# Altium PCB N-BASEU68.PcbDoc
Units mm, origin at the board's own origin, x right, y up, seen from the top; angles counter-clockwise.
Board outline 33.03 x 43.18 mm, 4 copper layers (Top Layer, Signal Layer 1, GND-PLANE, Bottom Layer), stack 1.583 mm thick; 51 components, 58 nets, 221 pads, 79 vias.
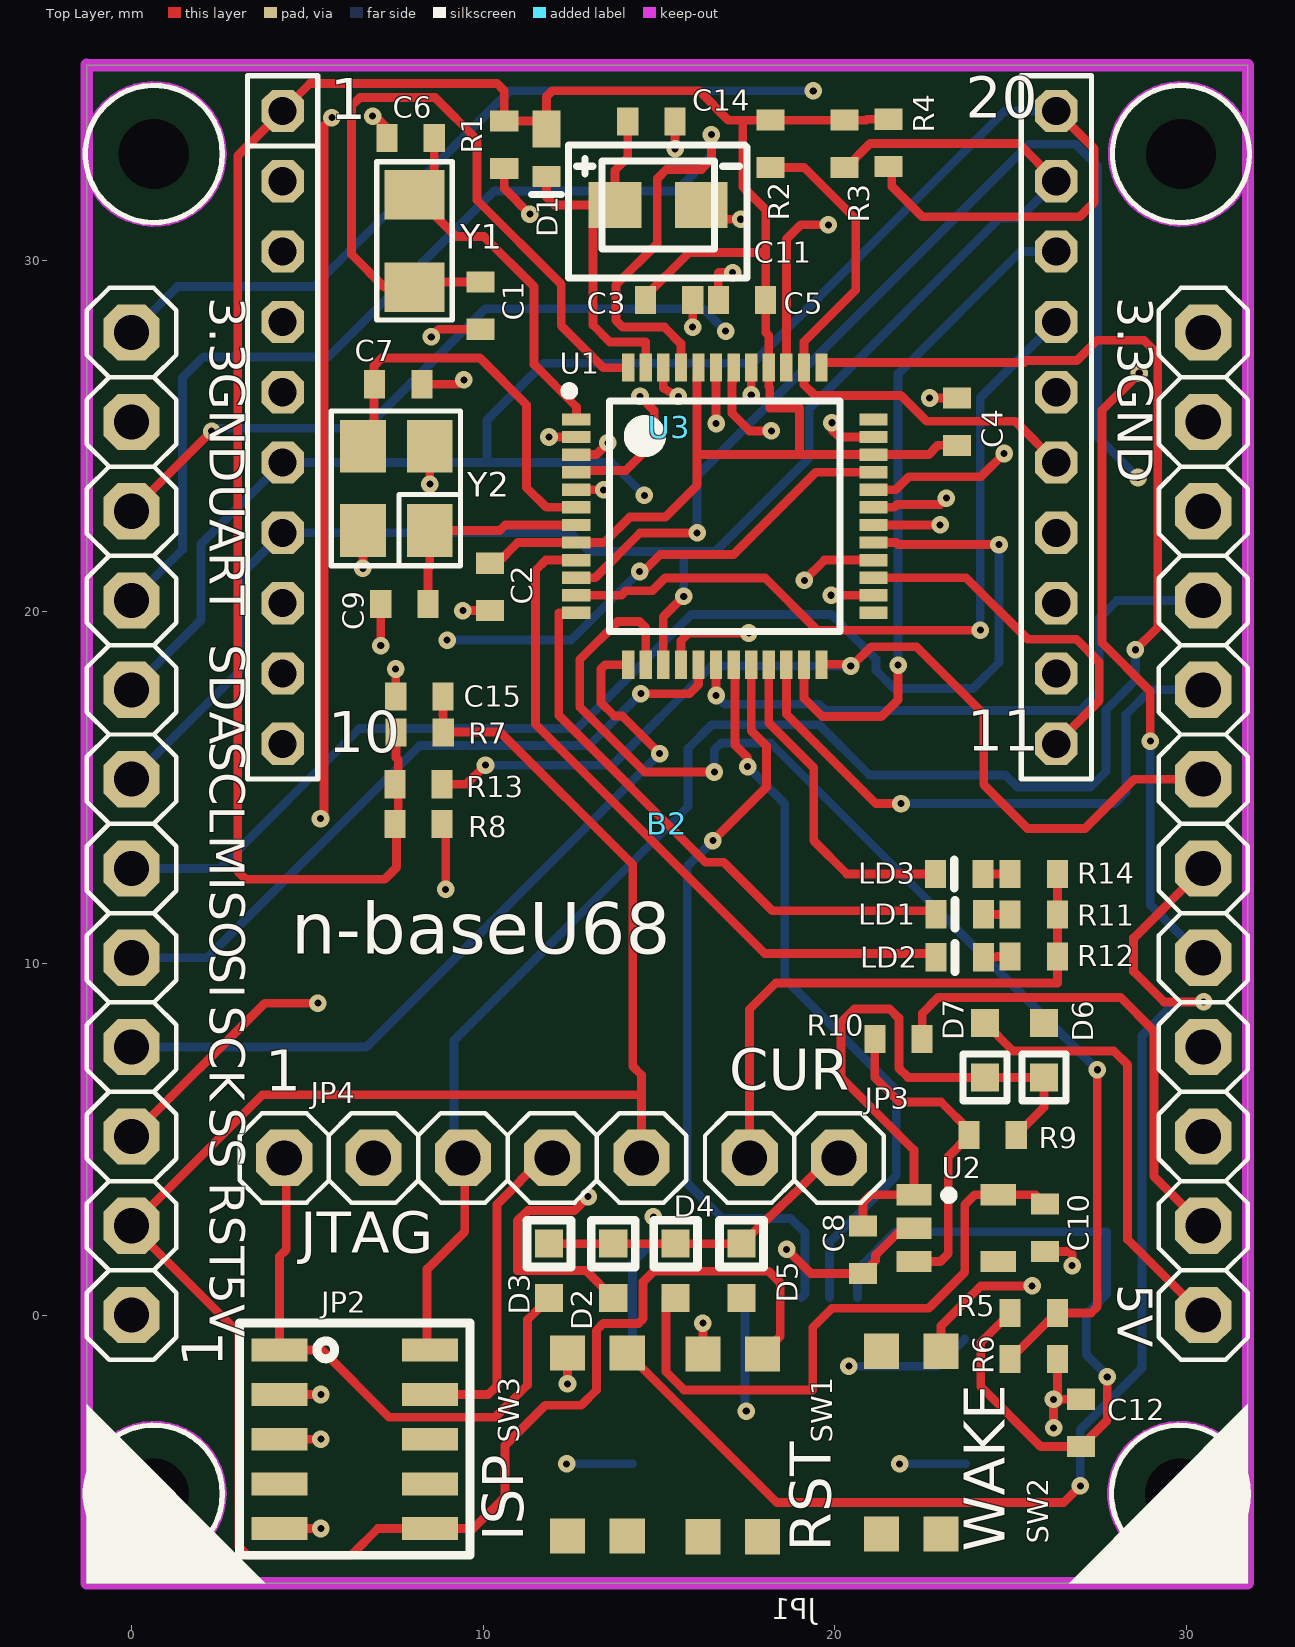
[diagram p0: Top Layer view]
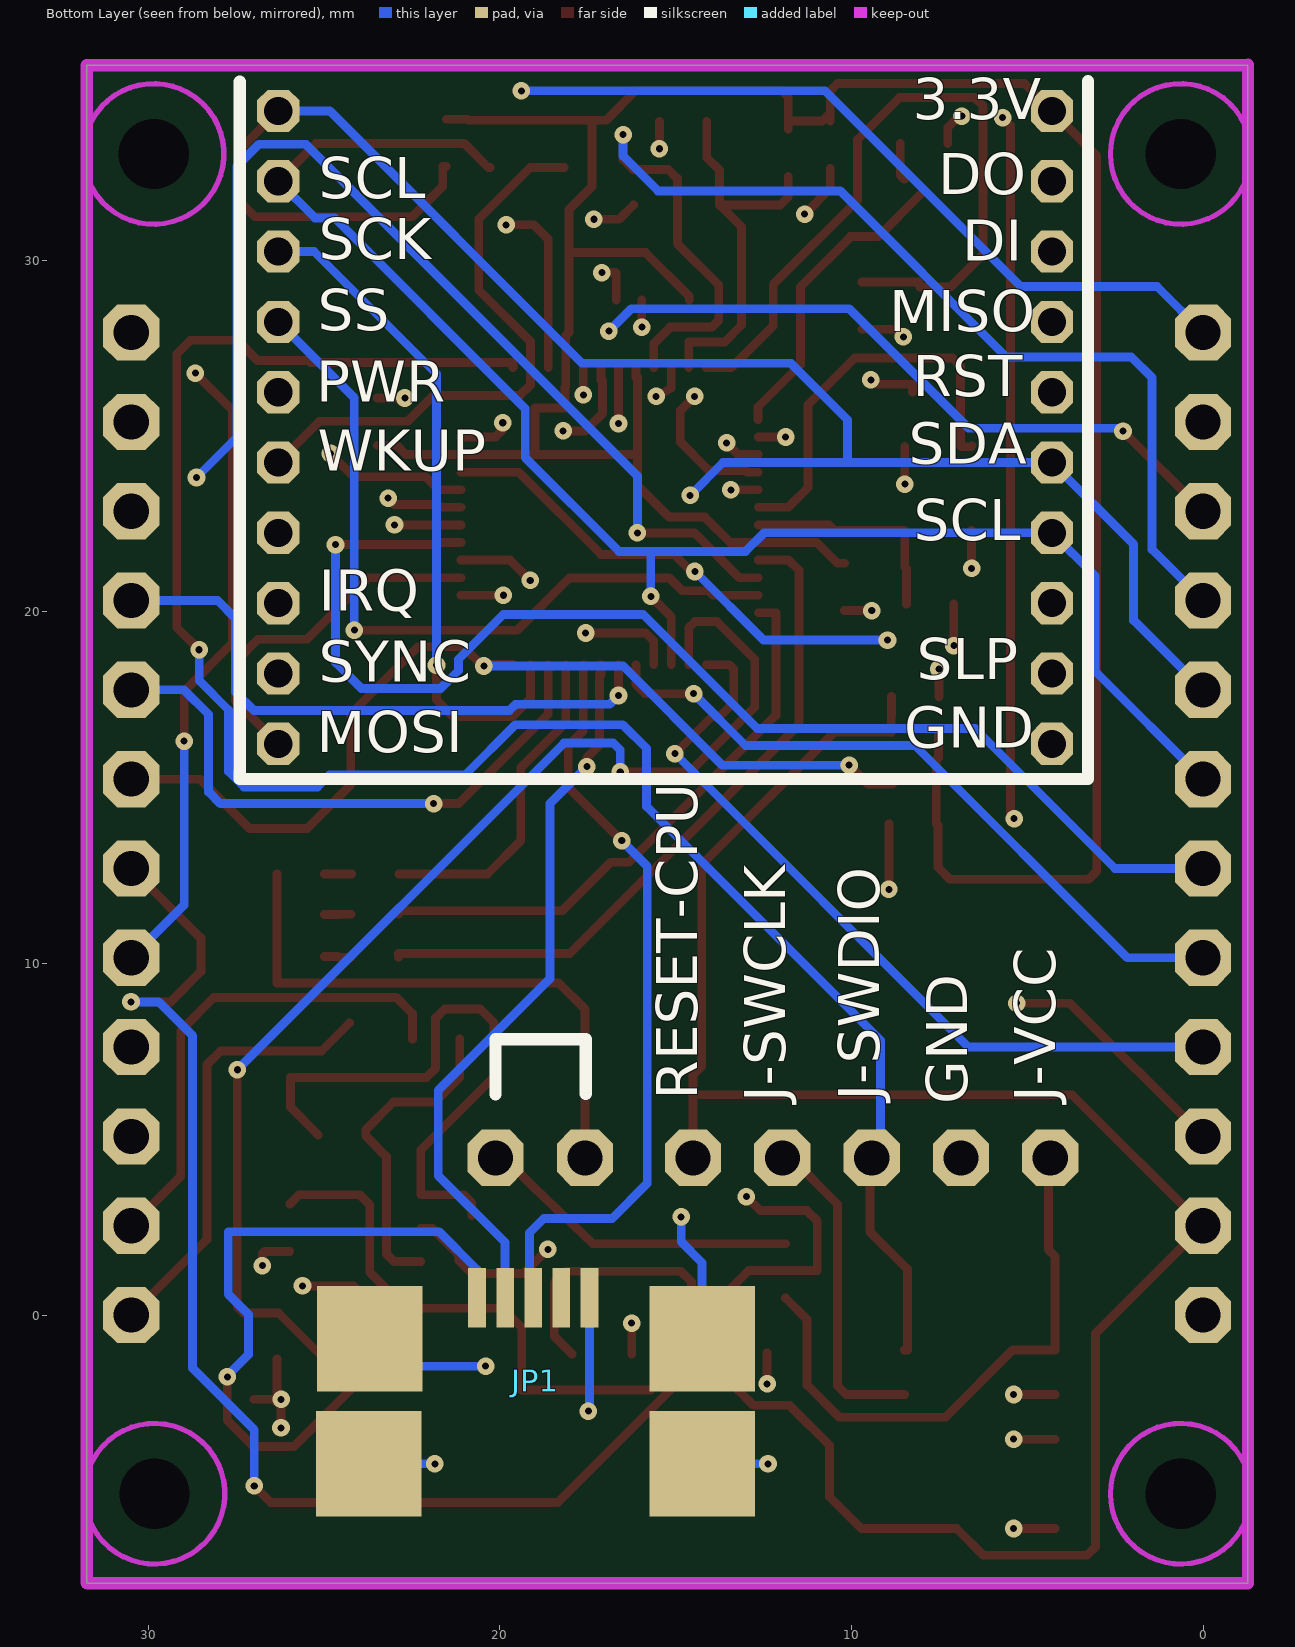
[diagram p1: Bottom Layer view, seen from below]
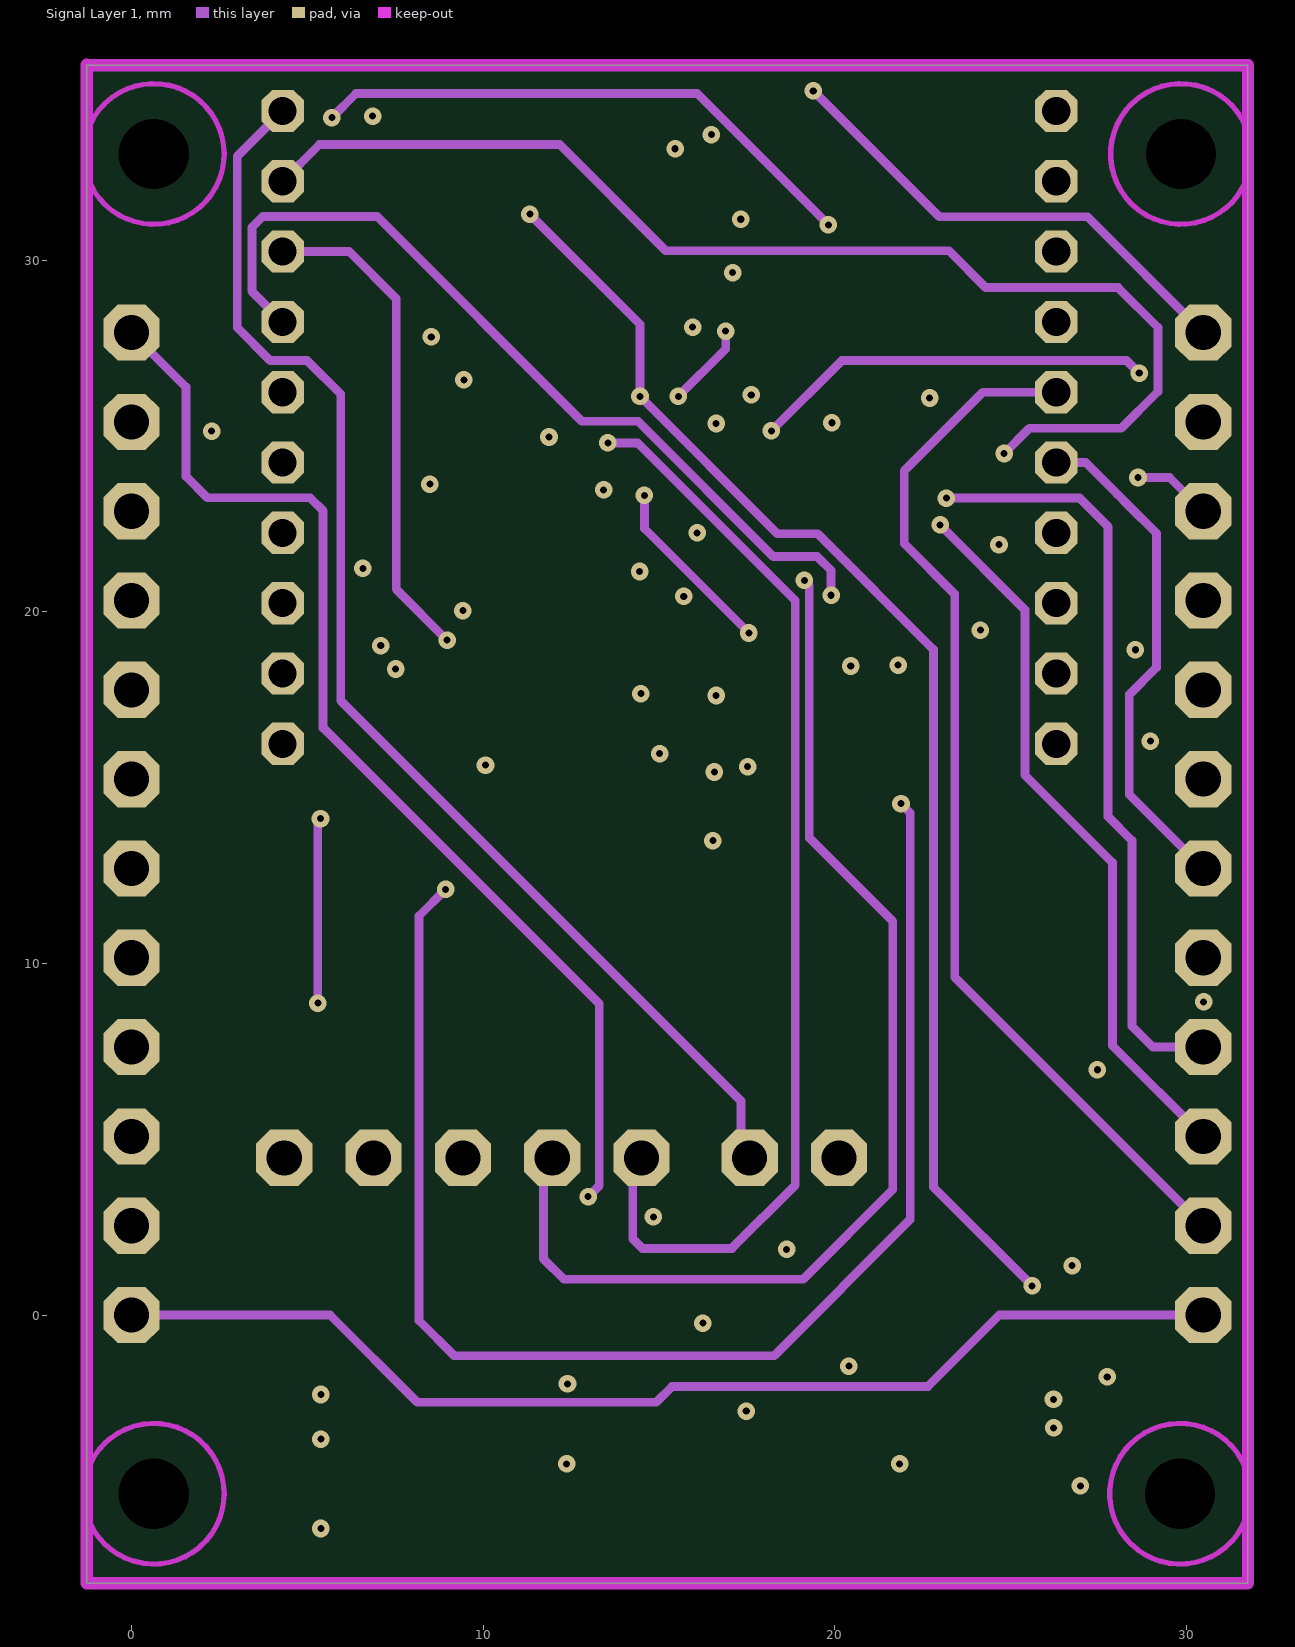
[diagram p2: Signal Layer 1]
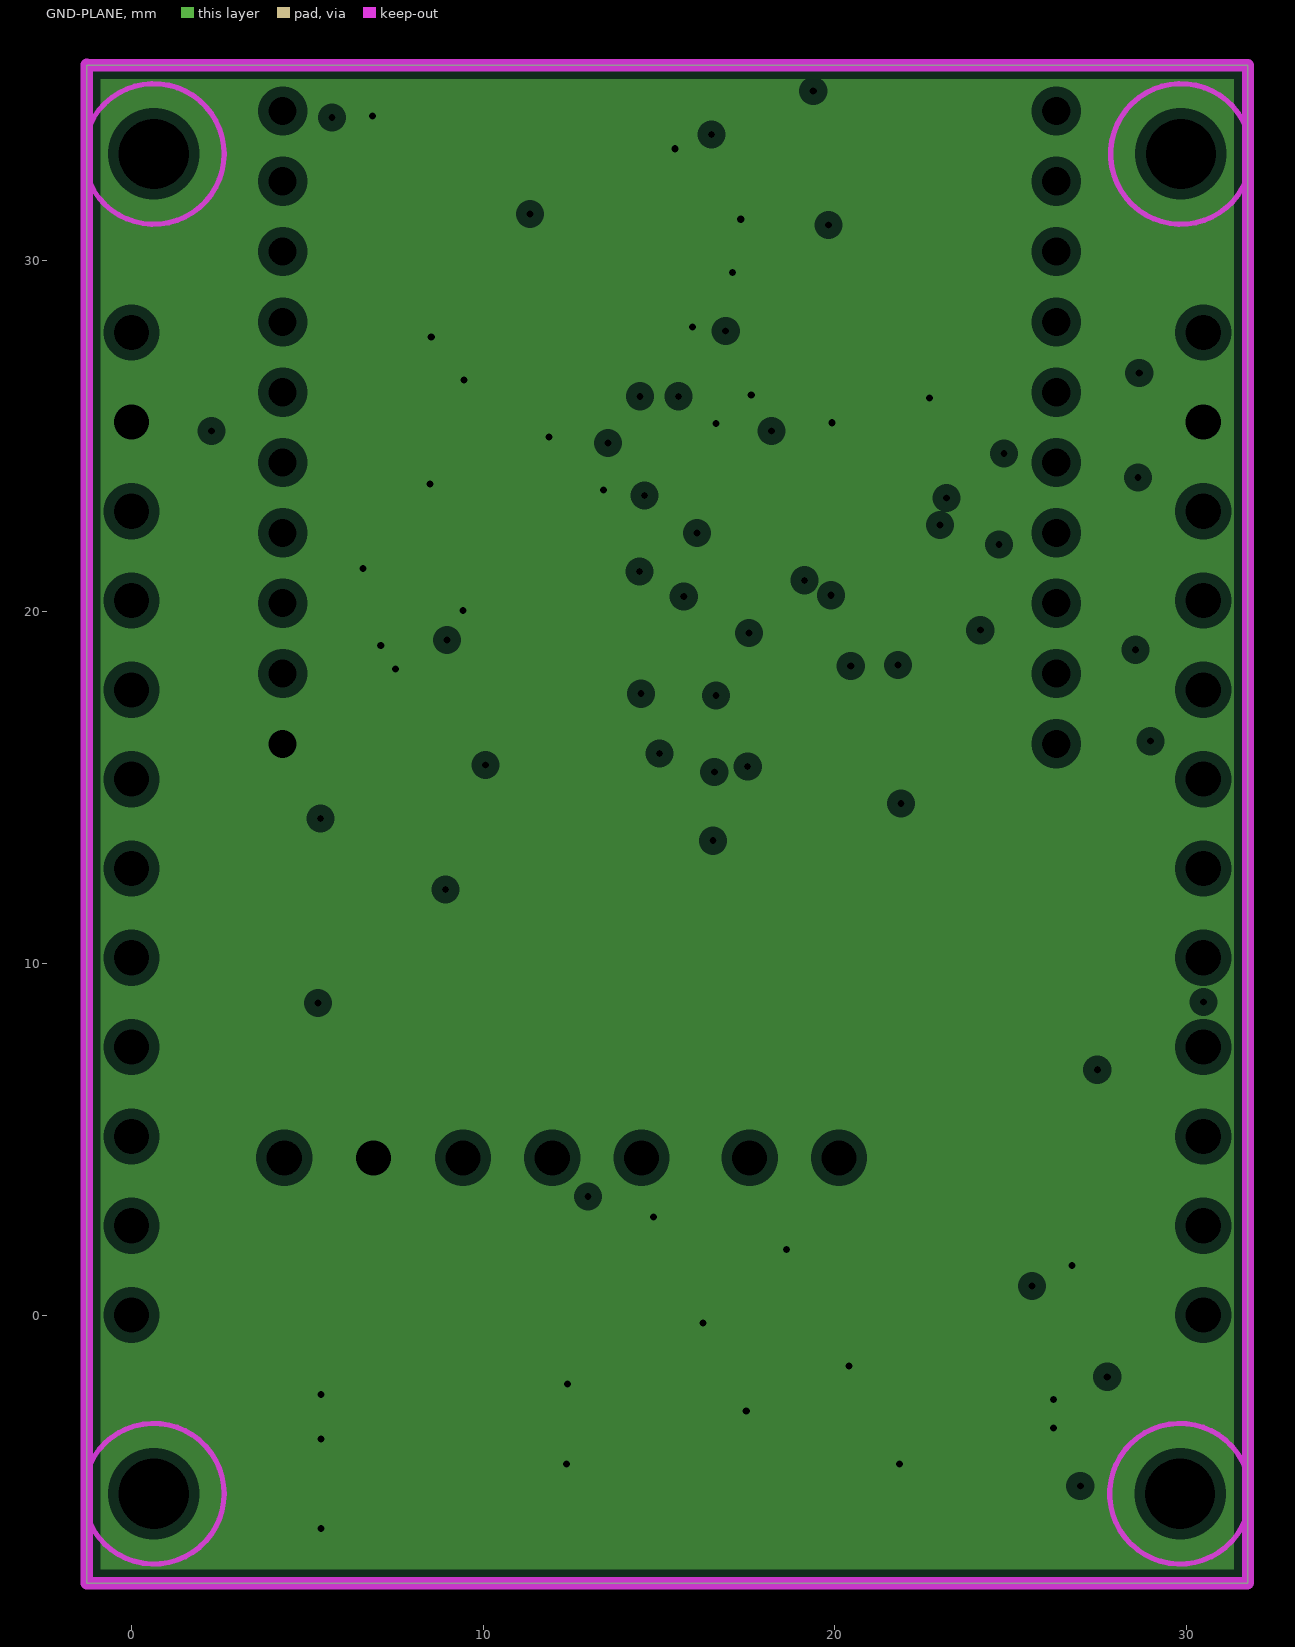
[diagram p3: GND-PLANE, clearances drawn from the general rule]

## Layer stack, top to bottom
Top Solder: solder mask 0.0102, Solder Resist, Dk 3.5
Top Layer: signal copper 0.0356
Dielectric1: core 0.48, FR-4, Dk 4.8
Signal Layer 1: signal copper 0.036
Dielectric 3: prepreg 0.48, Dk 4.2
GND-PLANE: plane copper 0.0356, net GND
Dielectric2: core 0.48, FR-4, Dk 4.2
Bottom Layer: signal copper 0.0356
Bottom Solder: solder mask 0.0102, Solder Resist, Dk 3.5

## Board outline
-1.275,-7.625 31.75,-7.625 31.75,35.55 -1.275,35.55

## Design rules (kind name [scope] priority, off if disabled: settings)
Clearance "Clearance IN CLASS 1mm" [(InNetClass('CL-1mm'))] p1 off: gap=1
Clearance Clearance_GND_PLANE [InNamedPolygon('GND_POLY_TOP')] p2 off: gap=0.4
Clearance Clearance_+5V_POLY [InNamedPolygon('poly_+5V-bottom')] p3 off: gap=0.5
Clearance [All] p4: gap=0.15
MinimumAnnularRing [All] p1: minimumring=0.149
PlaneClearance [All] p1: clearance=0.3
PlaneConnect Plane_ConnectStyle_1 [(Name = 'C1-1') Or (Name = 'C1-2') Or (Name = 'C2-1') Or (Name = 'C2-2') Or (Name = 'C3-1') Or (Name = 'C3-2') Or (Name = 'C4-1') Or (Name = 'C4-2') Or (Name = 'C5-1') Or (Name = 'C5-2') Or (Name = 'C6-1') Or (Name = 'C6-2') Or (Name = 'C7-1')] p1 off: planeconnectstyle=Relief reliefexpansion=1.27 reliefentries=4 reliefconductorwidth=0.381 reliefairgap=0.508
PlaneConnect [All] p2: planeconnectstyle=Direct reliefexpansion=0.635 reliefentries=4 reliefconductorwidth=0.305 reliefairgap=0.254
PolygonConnect [All] p1: connectstyle=Direct reliefconductorwidth=0.254 reliefentries=4 polygonreliefangle="90 Angle" airgapwidth=0.254
RoomDefinition N-BASEU68 [InComponentClass('N-BASEU68')] p1: confinementstyle=ConfineIn formatcopy=TRUE lockcomponents=FALSE outline -5.605,46.58 33.13,46.58 33.13,3.4 -5.605,3.4
RoutingVias VIASWITDTH2MM [(InNetClass('W-2mm'))] p1 off: holewidth=1 width=1.8 viastyle="Through Hole" minholewidth=0.4 minwidth=0.7 maxholewidth=1 maxwidth=1.8
RoutingVias VIASWITDTH1MM [(InNetClass('W-2mm'))] p2 off: holewidth=0.5 width=1 viastyle="Through Hole" minholewidth=0.5 minwidth=1 maxholewidth=0.5 maxwidth=1
RoutingVias VIASWITDTH1.5MM [(InNetClass('W-2mm'))] p3 off: holewidth=0.9 width=1.4 viastyle="Through Hole" minholewidth=0.9 minwidth=1.4 maxholewidth=0.9 maxwidth=1.4
RoutingVias [All] p4: holewidth=0.2 width=0.5 viastyle="Through Hole" minholewidth=0.2 minwidth=0.5 maxholewidth=0.2 maxwidth=0.5
SilkToSolderMaskClearance SilkscreenOverComponentPads [IsPad] p1: minsilkscreentomaskgap=0.254 clearancetoexposedcopper=TRUE
SolderMaskExpansion [All] p1: expansion=0
Width 12V_PLANE [(InNet('+12V')) and (IsPolygon)] p1 off: maxlimit=0.3 minlimit=0.2 preferedwidth=0.2
Width GND_PLANE [(InNet('GND'))  and (IsPolygon)] p2 off: maxlimit=0.3 minlimit=0.2 preferedwidth=0.2
Width WIDTH2MM [(InNetClass('W-2mm'))] p3 off: maxlimit=2 minlimit=0.25 preferedwidth=2
Width WIDTH1.5MM [(InNetClass('W-1.5mm'))] p4 off: maxlimit=2 minlimit=0.5 preferedwidth=1.5
Width "WIDTH 1MM" [(InNetClass('W-1mm'))] p5 off: maxlimit=2 minlimit=0.75 preferedwidth=1
Width WIDTH0.5MM [(InNetClass('W-0.5mm'))] p6 off: maxlimit=2 minlimit=0.25 preferedwidth=0.5
Width WIDTH0.25MM [(InNetClass('W-0.25mm'))] p7 off: maxlimit=2 minlimit=0.2 preferedwidth=0.25
Width [All] p8: maxlimit=2 minlimit=0.25 preferedwidth=0.25
27 further rules are at their usual default settings.

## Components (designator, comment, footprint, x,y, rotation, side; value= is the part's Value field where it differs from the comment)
B2 "N-GMS" N-GMS 0,33.025 r270 top locked
C1 "22pF" 0603_cap 9.925,28.725 r270 top
C2 "100nF" 0603_cap 10.2,20.725 r270 top
C3 "100nF" 0603_cap 15.275,28.875 r0 top
C4 "100nF" 0603_cap 23.475,25.4 r90 top
C5 "100nF" 0603_cap 17.375,28.875 r180 top
C6 "18pF" 0603_cap 7.95,33.475 r180 top
C7 "7pF" 0603_cap 7.575,26.475 r0 top
C8 "1uF/MLCC" 0603_CAP 20.8,1.85 r90 top
C9 "7pF" 0603_cap 7.775,20.225 r180 top
C10 "1uF/MLCC" 0603_CAP 25.975,2.475 r90 top
C11 "0.011F" "SUPERCAP  PAS3225P3R3113" 14.975,31.625 r0 top
C12 "100nF" 0603_cap 27,-3.05 r270 top
C14 "10uF/MLCC" 0603_CAP 14.8,33.95 r180 top
C15 "100nF" 0603_cap 8.2,17.6 r180 top
D1 "NSR20F30NXT5G" 0603_DIODE-CASE_152AB 11.8,33.075 r270 top
D2 "NSR20F30NXT5G" 0603_DIODE-CDSU101A 13.7,1.25 r90 top
D3 "NSR20F30NXT5G" 0603_DIODE-CDSU101A 11.875,1.25 r90 top
D4 "NSR20F30NXT5G" 0603_DIODE-CDSU101A 15.475,1.25 r90 top
D5 "NSR20F30NXT5G" 0603_DIODE-CDSU101A 17.35,1.25 r90 top
D6 "NSR20F30NXT5G" 0603_DIODE-CDSU101A 25.95,7.55 r270 top
D7 "NSR20F30NXT5G" 0603_DIODE-CDSU101A 24.275,7.55 r270 top
JP1 "USB-MINI-B" USB-MINI-B-HIR-UX60A-MB-5ST 17.4,-0.325 r0 bottom
JP2 "Header 5X2 1.27mm" 2x5-1.27mm-HARWIN-855-M50-3600542 6.35,-3.525 r270 top
JP3 "HEADER-2" 1X02 18.85,4.475 r180 top
JP4 "HEADER_5" 1X05 9.425,4.475 r0 top
LD1 "LED_RED" 0603_LED_RED 23.569,11.403 r180 top
LD2 "LED_GRN" 0603_LED_GRN 23.569,10.179 r180 top
LD3 "LED_BLU" 0603_LED_BLU 23.55,12.55 r180 top
R1 "10K" 0603_res 10.6,33.275 r90 top
R2 "10K" 0603_res 18.175,33.3 r90 top
R3 "10K" 0603_res 20.275,33.3 r90 top
R4 "10K" 0603_res 21.525,33.325 r90 top
R5 "10K" 0603_res 25.648,0.063 r0 top
R6 "18K" 0603_res 25.648,-1.245 r0 top
R7 "10K" 0603_res 8.206,16.57 r180 top
R8 "10K" 0603_res 8.175,13.975 r180 top
R9 "0R" 0603_res 24.475,5.125 r0 top
R10 "0R" 0603_res 21.8,7.856 r0 top
R11 "620R" 0603_res 25.65,11.4 r0 top
R12 "470R" 0603_res 25.65,10.2 r0 top
R13 "10K" 0603_res 8.175,15.1 r180 top
R14 "470R" 0603_res 25.65,12.55 r0 top
SW1 "EVQ-P2202M" BUTTON_4.7x3.5mm 16.95,-3.8 r0 top
SW2 "EVQ-P2202M" BUTTON_4.7x3.5mm 22.025,-3.725 r0 top
SW3 "EVQ-P2202M" BUTTON_4.7x3.5mm 13.1,-3.775 r0 top
U1 "LPC11U68JBD48" SOT313-2_V 12.45,25.475 r0 top
U2 "TPS78233" SOT23-5_0.95MM-NOSILK 23.45,2.475 r270 top
U3 "N-NODE24-20pin" N-NODE24-20pins 4.3,34.25 r0 top locked
Y1 "FC135-32.76KAA3" CRYSTAL-3.2X1.5 8.05,30.55 r270 top
Y2 "12MHz/10pF" CRY-SMD4-EPSON-FA238V 7.533,23.515 r90 top

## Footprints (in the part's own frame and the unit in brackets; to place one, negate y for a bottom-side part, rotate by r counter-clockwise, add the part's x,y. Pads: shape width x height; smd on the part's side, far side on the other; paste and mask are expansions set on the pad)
1X02 [mil]
  oct 63x63 hole 39.37: 1(-50,0) 2(50,0)
  silkscreen extent -100,-50 100,50, body extent -100,-50 100,50, height 398
1X05 [mil]
  oct 63x63 hole 39.37: 1(-200,0) 2(-100,0) 3(0,0) 4(100,0) 5(200,0)
  silkscreen extent -250,-50 250,50
2x5-1.27mm-HARWIN-855-M50-3600542 [mm]
  rect 0.65x1.6 smd paste+0: 1(-2.54,-2.14) 2(-2.54,2.14) 3(-1.27,-2.14) 4(-1.27,2.14) 5(0,-2.14) 6(0,2.14) 7(1.27,-2.14) 8(1.27,2.14) 9(2.54,-2.14) 10(2.54,2.14)
  silkscreen extent -3.3,-3.27 3.3,3.28, body extent -3.18,-2.75 3.18,2.75, height 4.5
0603_cap [mm]
  rect 0.6x0.8 smd: 1(-0.66,0) 2(0.686,0)
  body extent -0.8,-0.4 0.8,0.4, height 0.3
0603_CAP [mm]
  rect 0.6x0.8 smd: 1(-0.66,0) 2(0.686,0)
  body extent -0.8,-0.4 0.8,0.4, height 0.3
0603_DIODE-CASE_152AB [mm] "NSR20F30NXT5G"
  rect 1.05x0.8 smd: 1(-0.66,0)
  rect 0.6x0.8 smd: 2(0.686,0)
  silkscreen extent 1.2,-0.43 1.2,0.43, body extent -1.03,-0.51 0.77,0.49, height 0.85
0603_DIODE-CDSU101A [mm]
  rect 0.8x0.8 smd: 1(-0.76,0) 2(0.786,0)
  silkscreen extent 0.13,-0.63 1.45,0.63, body extent -0.9,-0.5 0.9,0.5, height 0.85
0603_LED_BLU [mm]
  rect 0.6x0.8 smd: 1(-0.66,0) 2(0.686,0)
  silkscreen extent 0.15,-0.4 0.15,0.4, body extent -0.81,-0.4 0.81,0.4, height 0.6
0603_LED_GRN [mm]
  rect 0.6x0.8 smd: 1(-0.66,0) 2(0.686,0)
  silkscreen extent 0.15,-0.4 0.15,0.4, body extent -0.81,-0.4 0.81,0.4, height 0.6
0603_LED_RED [mm]
  rect 0.6x0.8 smd: 1(-0.66,0) 2(0.686,0)
  silkscreen extent 0.15,-0.4 0.15,0.4, body extent -0.81,-0.4 0.81,0.4, height 0.6
0603_res [mm]
  rect 0.6x0.8 smd: 1(-0.66,0) 2(0.686,0)
  body extent -0.8,-0.4 0.8,0.4, height 0.3
BUTTON_4.7x3.5mm [mm] "TACTILE BUTTON 4.7x3.5mm Panasonic EVQ-P2202M"
  rect 1x1 smd: 1(-0.7,2.7) 2(1,2.7) 3(-0.7,-2.5) 4(1,-2.5)
  body extent -1.61,-2.63 1.89,2.87, height 2.15
CRY-SMD4-EPSON-FA238V [mm]
  rect 1.5x1.3 smd: 1(-1.2,-0.95) 2(1.2,-0.95) 3(1.2,0.95) 4(-1.2,0.95)
  silkscreen extent -2.2,-1.83 2.2,1.85, body extent -1.6,-1.25 1.6,1.25, height 0.77
CRYSTAL-3.2X1.5 [mm]
  rect 1.4x1.7 smd: 1(1.313,0) 2(-1.312,0)
  silkscreen extent -2.25,-1.07 2.25,1.07, body extent -1.58,-0.76 1.64,0.76, height 0.91
N-GMS [mil]
  round 39.37 hole 78.74 paste+0: 0(0,1175) 0(0,25) 0(1500,1174) 0(1500,25)
  oct 63x63 hole 39.37: 1(200,0) 2(300,0) 3(400,0) 4(500,0) 5(600,0) 6(700,0) 7(800,0) 8(900,0) 9(1000,0) 10(1100,0) 11(1200,0) 12(1300,0) 13(1300,1200) 14(1200,1200) 15(1100,1200) 16(1000,1200) 17(900,1200) 18(800,1200) 19(700,1200) 20(600,1200) 21(500,1200) 22(400,1200) 23(300,1200) 24(200,1200)
  Keep-Out Layer circle w5.91: c1500,25 r78.74
  Keep-Out Layer circle w5.91: c0,25 r78.74
  Keep-Out Layer circle w5.91: c0,1175 r78.74
  Keep-Out Layer circle w5.91: c1500,1174 r78.74
  silkscreen extent -77,-52 1600,1252, body extent -75,-51 1577,1251, height 335
N-NODE24-20pins [mm]
  oct 1.2x1.2 hole 0.8: 1(0,0) 2(0,-2) 3(0,-4) 4(0,-6) 5(0,-8) 6(0,-10) 7(0,-12) 8(0,-14) 9(0,-16) 10(0,-18) 11(22,-18) 12(22,-16) 13(22,-14) 14(22,-12) 15(22,-10) 16(22,-8) 17(22,-6) 18(22,-4) 19(22,-2) 20(22,0)
  silkscreen extent -1,-19 23,1, body extent -1,-19 23,1, height 4.5
SOT23-5_0.95MM-NOSILK [mm]
  rect 0.6x1 smd: 1(-0.95,-1.2) 2(0,-1.2) 3(0.95,-1.2) 4(0.95,1.2) 5(-0.95,1.2)
  silkscreen extent -1.06,-0.33 -0.81,-0.08, body extent -1.45,-1.4 1.45,1.4, height 1.45
SOT313-2_V [mm] "Thin QFP, 48-Leads, Body 7x7mm, Pitch 0.5mm, NXP Recommended"
  rect 0.8x0.35 smd: 1(0.2,0) 2(0.2,-0.5) 3(0.2,-1) 4(0.2,-1.5) 5(0.2,-2) 6(0.2,-2.5) 7(0.2,-3) 8(0.2,-3.5) 9(0.2,-4) 10(0.2,-4.5) 11(0.2,-5) 12(0.2,-5.5) 25(8.65,-5.5) 26(8.65,-5) 27(8.65,-4.5) 28(8.65,-4) 29(8.65,-3.5) 30(8.65,-3) 31(8.65,-2.5) 32(8.65,-2) 33(8.65,-1.5) 34(8.65,-1) 35(8.65,-0.5) 36(8.65,0)
  rect 0.35x0.8 smd: 13(1.675,-6.975) 14(2.175,-6.975) 15(2.675,-6.975) 16(3.175,-6.975) 17(3.675,-6.975) 18(4.175,-6.975) 19(4.675,-6.975) 20(5.175,-6.975) 21(5.675,-6.975) 22(6.175,-6.975) 23(6.675,-6.975) 24(7.175,-6.975) 37(7.175,1.475) 38(6.675,1.475) 39(6.175,1.475) 40(5.675,1.475) 41(5.175,1.475) 42(4.675,1.475) 43(4.175,1.475) 44(3.675,1.475) 45(3.175,1.475) 46(2.675,1.475) 47(2.175,1.475) 48(1.675,1.475)
  silkscreen extent -0.12,-6.02 7.7,0.93, body extent -0.07,-7.25 8.93,1.75, height 1.6
"SUPERCAP  PAS3225P3R3113" [mm]
  rect 1.5x1.3 smd: 1(-1.225,-0.05) 2(1.225,-0.05)
  silkscreen extent -2.32,-1.3 2.31,1.28, body extent -1.7,-1.4 1.7,1.3, height 0.9
USB-MINI-B-HIR-UX60A-MB-5ST [mm]
  rect 0.5x1.7 smd: 1(3.25,-0.825) 2(2.45,-0.825) 3(1.65,-0.825) 4(0.85,-0.825) 5(0.05,-0.825)
  rect 3x3 smd: 6(-3.15,3.9) 7(6.325,3.9) 8(-3.15,0.35) 9(6.3,0.35)
  body extent -3.3,-1.15 6.6,7.85, height 4.6

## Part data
C1 C2 C3 C4 C5 C6 C7 C8 C9 C10 C12 C14 C15: library part C, "CAPACITOR"
C11: library part CP_SUPERCAP
D1 D2 D3 D4 D5 D6 D7: library part DIODE, "DIODE"
JP2: library part "Header 5X2", "Header, 5-Pin, Dual row"
LD1 LD2 LD3: library part LED
R1 R2 R3 R4 R5 R6 R7 R8 R9 R10 R11 R12 R13 R14: library part R, "RESISTOR"
SW1 SW2 SW3: library part BUTTON_TACT, "BUTTON TACTILE"
U1: library part LPC11U68JBD48_1
U2: library part NCP702N
Y1: library part XTAL, "CRYSTAL"
Y2: library part XTAL_4PINS, "CRYSTAL"

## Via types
v1: diameter 0.5, hole 0.2, Top Layer to Bottom Layer, tented both sides, 77 vias
v2: diameter 0.5, hole 0.2, Top Layer to Bottom Layer, 2 vias

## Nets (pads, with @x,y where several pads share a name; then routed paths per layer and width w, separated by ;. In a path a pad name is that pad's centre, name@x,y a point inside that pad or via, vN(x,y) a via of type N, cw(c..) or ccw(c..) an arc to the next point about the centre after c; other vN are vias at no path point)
3.3V: C2.1 C3.1 C4.1 C5.1 D1.1 JP3.2 R1.2 R2.2 R3.2 R4.2 R7.2 R8.2 R11.2 R12.2 R13.2 R14.2 U1.8 U1.34 U1.40 U1.44 U3.1 | length 136.5
  Top Layer w0.25: R7.2 7.521,15.864 7.589,15.795 7.589,13.975 7.539,13.925 7.539,12.739 7.2,12.4 3.25,12.4 3.025,12.625 3.025,32.975 U3.1 5.077,35.027 10.398,35.027 10.6,34.825 R1.2@10.6,34.19 ; C2.1 10.397,21.385 10.987,21.975 U1.8 13.445,21.975 14.167,22.697 15.181,22.697 16.087,23.603 U1.44@16.087,26.628 ; R1.2 R1.2@10.6,34.19 ; D1.1 D1.1@11.8,33.961 ; C3.1 14.615,28.978 15.859,30.222 18.025,30.222 ; 16.087,24.475 19,24.475 ; U1.44 U1.44@16.125,26.666 ; JP3.2@17.33,4.475 17.575,4.72 17.575,8.698 18.327,9.45 26.336,9.45 R12.2 R11.2 R14.2 ; 17.386,33.986 17.382,33.982 17.382,32.093 18.035,31.44 C5.1 18.035,27.95 18.125,27.86 U1.40 18.125,26.415 18.15,26.39 18.15,25.8 19,25.8 19,24.475 ; R4.2 20.912,34.011 20.887,33.986 R3.2 R2.2 16.976,33.986 16.142,34.82 11.97,34.82 11.8,34.65 D1.1@11.8,33.961 ; C4.1 22.934,24.74 22.67,24.475 U1.34 19,24.475 ; R1.2@10.6,34.19 10.829,33.961 D1.1@11.8,33.961 ; U1.44@16.087,26.628 U1.44@16.125,26.666 ; U1.44@16.087,26.628 16.087,26.666 U1.44@16.125,26.666
  Signal Layer 1 w0.25: U3.1 3.005,32.955 3.005,28.089 3.945,27.149 5.001,27.149 5.952,26.198 5.952,17.473 17.33,6.095 JP3.2@17.33,4.475
3.3V-FTDI: D5.1
3.3V-GMS: B2.1 B2.24 D2.1 | length 74.9
  Top Layer w0.25: v1(12.988,3.375) 12.588,2.975 11.267,2.975 10.975,2.683 10.975,1.275 12.915,1.275 D2.1
  Signal Layer 1 w0.25: B2.1 1.55,26.395 1.55,23.855 2.155,23.25 5.075,23.25 5.45,22.875 5.45,16.704 13.3,8.854 13.3,3.687 v1(12.988,3.375) ; v1(19.389,34.82) 22.97,31.238 27.187,31.238 B2.24
  Bottom Layer w0.25: B2.1 1.312,29.257 5.19,29.257 10.753,34.82 v1(19.389,34.82)
5V-GMS: B2.12 B2.13 D7.1 | length 45.1
  Top Layer w0.25: D7.1 25.071,7.515 27.935,7.515 28.329,7.121 28.329,2.156 B2.13
  Signal Layer 1 w0.25: B2.12 5.645,0.005 8.127,-2.477 14.923,-2.477 15.375,-2.025 22.65,-2.025 24.68,0.005 B2.13
#PWROFF: B2.14 R10.2 U3.16 | length 44.3
  Top Layer w0.25: R10.2 22.486,8.582 22.943,9.039 28.126,9.039 29.075,8.09 29.075,3.95 B2.14
  Signal Layer 1 w0.25: U3.16 24.208,26.25 21.975,24.017 21.975,21.946 23.413,20.508 23.413,9.612 B2.14
BLUE: LD3.2 U1.21 | length 9.4
  Top Layer w0.25: U1.21 18.125,16.85 19.404,15.571 19.404,13.496 20.35,12.55 LD3.2
GND: B2.2 B2.23 C1.2 C2.2 C3.2 C4.2 C5.2 C6.2 C7.2 C8.1 C9.2 C10.1 C11.2 C12.1 C14.1 C15.2 JP1.5 JP1.6 JP1.7 JP1.8 JP1.9 JP2.3 JP2.5 JP2.9 JP4.2 R6.2 SW1.1 SW3.1 U1.2 U1.5 U1.35 U1.41 U1.43 U2.2 U3.10 Y2.2 Y2.4 | length 46.8
  Top Layer w0.25: JP2.9 v1(5.387,-6.065) ; JP2.5 v1(5.387,-3.525) ; JP2.3 v1(5.387,-2.255) ; v1(6.583,21.238) Y2.4 ; v1(6.858,34.102) 6.941,34.102 7.264,33.778 C6.2@7.264,33.325 ; v1(7.089,19.042) C9.2 ; C15.2 v1(7.514,18.377) ; C7.2@8.261,26.25 C7.2 9.275,26.475 9.425,26.625 v2(9.45,26.6) ; v1(8.483,23.638) Y2.2 ; v2(8.525,27.825) 8.739,28.039 C1.2@9.7,28.039 ; v1(9.423,20.039) C2.2 ; v1(11.873,24.975) U1.2 ; v1(12.4,-1.952) SW3.1 ; U1.5 v1(13.427,23.475) ; v1(15.46,33.173) C14.1 ; v1(15.961,28.098) C3.2 ; C11.2 16.606,31.169 v1(17.327,31.169) ; SW1.1 v1(16.25,-0.223) ; v1(16.625,25.36) U1.43 ; C5.2 16.689,29.639 16.702,29.652 v1(17.096,29.652) ; v1(17.625,26.173) U1.41 ; v1(18.633,1.876) 19.319,1.19 C8.1 21.16,1.55 21.16,1.7 ; v1(19.917,25.381) 19.917,25.184 20.125,24.975 U1.35 ; 21.175,1.7 21.175,1.725 21.925,2.475 U2.2 ; v1(22.698,26.086) C4.2 ; C10.1 26.685,1.815 26.752,1.748 v1(26.752,1.408) ; v1(26.221,-2.391) 26.334,-2.279 R6.2 ; v1(26.223,-3.202) 26.223,-2.594 26.428,-2.39 C12.1
  Bottom Layer w0.25: v1(12.373,-4.225) JP1.6 ; JP1.8 14.25,1.495 14.842,2.087 v1(14.842,2.796) ; JP1.5 17.45,-2.693 v1(17.484,-2.727) ; v1(20.401,-1.45) 22.925,-1.45 JP1.9 ; v1(21.848,-4.225) JP1.7
GREEN: LD2.2 U1.9 | length 19.9
  Top Layer w0.25: U1.9 11.784,21.475 11.489,21.18 11.489,16.811 18.017,10.283 22.883,10.283 LD2.2
I2C0_SCL: B2.6 R3.1 U1.15 U3.7 U3.19 | length 46.4
  Top Layer w0.25: U1.15 15.125,19.863 v1(15.706,20.443) ; R3.1 20.328,32.64 21.014,33.325 25.225,33.325 U3.19
  Bottom Layer w0.25: B2.6 3.075,18.32 3.075,21.025 U3.7 12.484,22.25 13.012,21.722 15.75,21.722 ; v1(15.706,20.443) 15.706,21.677 15.75,21.722 ; U3.19 25.257,31.207 24.701,31.207 19.277,25.782 19.277,24.387 16.612,21.722 15.75,21.722
I2C0_SDA: B2.5 R4.1 U1.16 U3.6 U3.20 | length 57.8
  Top Layer w0.25: U1.16 15.625,19.175 15.852,19.402 v1(17.56,19.402) ; R4.1 21.624,32.665 21.624,32.102 22.487,31.238 26.963,31.238 27.375,31.65 27.375,33.175 U3.20
  Signal Layer 1 w0.25: v1(14.588,23.314) 14.588,22.374 v1(17.56,19.402)
  Bottom Layer w0.25: B2.5 1.975,19.76 1.975,21.925 U3.6 10.114,24.25 ; v1(14.588,23.314) 13.652,24.25 10.114,24.25 ; U3.20 24.841,34.25 17.664,27.073 11.723,27.073 10.114,25.464 10.114,24.25
I2C1_SCL: B2.19 R13.1 U1.24 | length 28
  Top Layer w0.25: R13.1 9.524,15.1 v1(10.067,15.643) ; U1.24 19.625,18.513 20.405,18.513 v1(20.455,18.462) 20.487,18.462 21.038,19.013 22.327,19.013 24.24,17.099 24.24,15.084 25.485,13.839 27.114,13.839 28.52,15.245 B2.19
  Bottom Layer w0.25: v1(10.067,15.643) 13.674,15.643 16.494,18.462 v1(20.455,18.462)
I2C1_SDA: B2.20 R8.1 U1.22 | length 59.3
  Top Layer w0.25: v1(8.935,12.112) R8.1@8.935,13.975 ; U1.22 18.625,17.1 21.174,14.551 v1(21.883,14.551)
  Signal Layer 1 w0.25: v1(8.935,12.112) 8.175,11.352 8.175,-0.15 9.175,-1.15 18.275,-1.15 22.15,2.725 22.15,14.284 v1(21.883,14.551)
  Bottom Layer w0.25: v1(21.883,14.551) 27.951,14.551 28.283,14.883 28.283,17.083 28.985,17.785 B2.20
IRQ: U3.13
ISP: R1.1 SW2.2 U1.4 | length 46.3
  Top Layer w0.25: R1.1 10.6,32.046 v1(11.331,31.315) ; U1.4 12.962,23.975 13.012,24.025 14.055,24.025 14.867,24.838 14.867,25.727 v1(14.461,26.133) ; SW2.2 23.025,-0.3 24.16,0.835 v1(25.612,0.835)
  Signal Layer 1 w0.25: v1(11.331,31.315) 14.461,28.185 v1@14.461,26.359 ; v1(14.461,26.133) 18.369,22.225 19.512,22.225 22.807,18.93 22.807,3.639 v1(25.612,0.835)
J-VCC: D3.1 JP2.1 JP4.1 | length 16.6
  Top Layer w0.25: JP4.1@4.095,4.475 4.4,4.17 4.4,1.863 4.21,1.673 JP2.1 5.41,-0.985 7.325,-2.9 10.345,-2.9 11.261,-1.985 11.261,-0.125 D3.1
MISO0: U1.26 U3.4 | length 25.7
  Top Layer w0.25: v1(19.897,20.475) U1.26
  Signal Layer 1 w0.25: U3.4 3.425,29.125 3.425,30.934 3.741,31.25 6.982,31.25 12.81,25.422 14.403,25.422 18.25,21.575 19.502,21.575 19.897,21.18 v1(19.897,20.475)
MOSI0: U1.27 U3.11 | length 10.3
  Top Layer w0.25: U1.27 23.734,20.975 25.484,19.225 26.875,19.225 27.525,18.575 27.525,17.475 U3.11
NetC8_2: C8.2 D6.2 D7.2 R9.2 U2.1 | length 17.2
  Top Layer w0.25: C8.2@20.8,2.836 20.8,3.2 21.025,3.425 U2.1 22.25,4.7 20.175,6.775 20.175,8.325 20.559,8.709 21.566,8.709 21.825,8.45 21.825,7.025 22.086,6.764 D7.2 D6.2 25.95,5.914 R9.2
NetC10_2: C10.2 D4.1 U2.5 | length 17.9
  Top Layer w0.25: D4.1 15.2,0.49 15.2,-1.609 15.716,-2.125 19.375,-2.125 19.375,-0.347 19.922,0.2 22.675,0.2 23.7,1.225 23.7,3.139 23.986,3.425 U2.5 25.711,3.425 C10.2
NetD2_2: D2.2 D3.2 D4.2 D5.2 JP3.1 | length 9
  Top Layer w0.25: D3.2 D2.2 D4.2 D5.2 19.049,3.654 JP3.1@19.87,4.475
NetLD1_1: LD1.1 R11.1 | length 0.8
  Top Layer w0.25: LD1.1 24.596,11.403 24.599,11.4 R11.1
NetLD2_1: LD2.1 R12.1 | length 0.8
  Top Layer w0.25: LD2.1 24.596,10.179 24.617,10.2 R12.1
NetLD3_1: LD3.1 R14.1 | length 0.8
  Top Layer w0.25: LD3.1 R14.1
NetR5_2: R5.2 R6.1 U1.14 | length 34.7
  Top Layer w0.25: U1.14 14.625,19.55 14.45,19.725 13.825,19.725 12.75,18.65 12.75,17.298 14.6,15.448 v1(16.575,15.448) ; R6.1 26.295,0.063 R5.2 27.288,0.063 27.466,0.241 v1(27.466,6.981)
  Bottom Layer w0.25: v1(16.575,15.448) 16.575,16.075 16.775,16.275 18.172,16.275 v1(27.466,6.981)
NetR9_1: R9.1 R10.1 U2.3 | length 9.2
  Top Layer w0.25: R10.1 21.14,6.76 21.836,6.064 23.022,6.064 23.815,5.272 R9.1 23.815,5.102 23.225,4.512 23.225,1.75 23,1.525 U2.3
PIO0_11/ADC9: B2.15 U1.30 | length 22.4
  Top Layer w0.25: U1.30 v1(22.995,22.475)
  Signal Layer 1 w0.25: v1(22.995,22.475) 25.408,20.062 25.408,15.363 27.9,12.872 27.9,7.665 B2.15
PIO0_12/ADC8: B2.16 U1.31 | length 23.9
  Top Layer w0.25: U1.31 21.692,22.975 21.775,23.058 22.994,23.058 v1(23.173,23.237)
  Signal Layer 1 w0.25: v1(23.173,23.237) 26.963,23.237 27.775,22.425 27.775,14.174 28.45,13.499 28.45,8.225 29.05,7.625 B2.16
PIO1_13: U1.36
PIO1_17: B2.17 U1.42 | length 32.4
  Top Layer w0.25: U1.42 17.125,26.59 17.077,26.59 17.077,25.65 17.578,25.15 v1(18.2,25.15) ; v1(28.66,26.793) 27.601,25.735 27.601,19.124 28.975,17.75 v1(28.975,16.325)
  Signal Layer 1 w0.25: v1(18.2,25.15) 20.199,27.149 28.304,27.149 v1(28.66,26.793)
  Bottom Layer w0.25: v1(28.975,16.325) 28.975,11.67 B2.17
RED: LD1.2 U1.12 | length 16.6
  Top Layer w0.25: U1.12 12.15,19.975 12.15,17.058 16.325,12.883 16.842,12.883 18.222,11.503 22.883,11.503 LD1.2
RESET-CPU: B2.11 C15.1 JP2.10 JP4.5 R7.1 SW1.2 U1.3 | length 99.2
  Top Layer w0.25: C15.1 8.86,17.072 8.867,17.065 R7.1@8.867,16.583 ; R7.1 R7.1@8.867,16.583 ; U1.3 13.216,24.475 v1(13.549,24.808) ; JP4.5 14.505,6.271 ; SW1.2 18.45,-0.6 18.45,0.925 18.125,1.25 14.851,1.25 14.55,0.949 14.55,-0.1 14.418,-0.232 13.42,-0.232 13.225,-0.427 13.225,-2.125 12.79,-2.56 11.765,-2.56 10.625,-3.7 10.625,-5.16 9.72,-6.065 JP2.10 7.012,-6.065 6.252,-6.825 3.3,-6.825 3.056,-6.581 3.056,-0.511 B2.11 3.726,6.271 14.505,6.271 ; R7.1@8.867,16.583 10.492,16.583 14.255,12.82 14.255,7.08 14.505,6.83 14.505,6.271
  Signal Layer 1 w0.25: v1(13.549,24.808) 14.392,24.808 18.875,20.325 18.875,3.7 17.075,1.9 14.525,1.9 14.255,2.17 JP4.5@14.255,4.475
RESET-TGT: U3.5
RTC-BAT: C11.1 C14.2 D1.2 U1.47 | length 11.3
  Top Layer w0.25: D1.2 11.8,31.8 12.025,31.575 C11.1 ; C14.2 14.114,32.923 13.75,32.559 C11.1 ; U1.47 14.625,27.675 13.609,27.675 13.125,28.159 13.125,30.95 C11.1
RTCXIN: C1.1 U1.48 Y1.1 | length 20.9
  Top Layer w0.25: Y1.1 7.191,29.237 6.257,30.172 6.257,34.388 6.496,34.627 8.634,34.627 9.825,33.436 9.825,31.716 12.225,29.316 12.225,28.14 13.42,26.946 14.125,26.946 U1.48 ; Y1.1@8.085,29.385 C1.1@9.7,29.385
RTCXOUT: C6.1 U1.1 Y1.2 | length 9.8
  Top Layer w0.25: Y1.2 9.237,30.675 10.025,30.675 11.45,29.25 11.45,27.036 12.658,25.828 12.658,25.475 U1.1 ; Y1.2@8.494,32.306 8.61,32.423 C6.1@8.61,33.325
RX1: U1.32 U3.2 | length 38.6
  Top Layer w0.25: U1.32 21.734,23.475 22.106,23.847 24.156,23.847 v1(24.816,24.507)
  Signal Layer 1 w0.25: U3.2 5.346,33.296 12.175,33.296 15.198,30.273 23.249,30.273 24.298,29.225 28.057,29.225 29.193,28.089 29.193,26.268 28.15,25.225 25.534,25.225 v1(24.816,24.507)
RX2: B2.22 U1.10 | length 32.7
  Top Layer w0.25: U1.10 13.189,20.975 14.461,22.247 v1(16.087,22.247)
  Signal Layer 1 w0.25: v1(28.625,23.825) 29.52,23.825 B2.22
  Bottom Layer w0.25: v1(16.087,22.247) 16.087,23.872 25.514,33.3 26.852,33.3 27.475,32.677 27.475,24.975 v1(28.625,23.825)
RXD0: B2.4 U1.45 | length 35
  Top Layer w0.25: U1.45 15.625,27.632 15.157,28.1 13.975,28.1 13.775,28.3 13.775,29.297 14.95,30.472 14.95,32.325 15.21,32.585 16.21,32.585 16.493,32.868 v1(16.493,33.575)
  Bottom Layer w0.25: B2.4 1.45,21.775 1.45,26.66 2.04,27.251 5.596,27.251 10.321,31.975 15.502,31.975 16.493,32.966 v1(16.493,33.575)
SCK0: U1.23 U3.18 | length 19.2
  Top Layer w0.25: U1.23 19.125,17.55 19.65,17.025 21.325,17.025 21.802,17.502 v1(21.802,18.488)
  Bottom Layer w0.25: v1(21.802,18.488) 21.802,26.768 25.284,30.25 U3.18
SLEEP: U3.9
SS0: U1.11 U3.17 | length 22
  Top Layer w0.25: U1.11 13.934,20.475 14.061,20.602 14.814,20.602 15.181,20.968 18.017,20.968 19.504,19.481 v1(24.138,19.481)
  Bottom Layer w0.25: v1(24.138,19.481) 24.138,26.088 U3.17
SSP1_MISO/ADC11: B2.7 U1.29 | length 36
  Top Layer w0.25: U1.29 21.751,21.975 21.809,21.917 v1(24.672,21.917)
  Bottom Layer w0.25: B2.7 2.506,12.705 6.485,16.684 12.679,16.684 15.921,19.927 19.905,19.927 21.175,18.657 21.175,18.335 21.682,17.827 23.935,17.827 24.672,18.564 v1(24.672,21.917)
SSP1_MOSI: B2.8 U1.17 | length 19.9
  Top Layer w0.25: v1(14.486,17.675) 15.871,17.675 16.125,17.929 U1.17
  Bottom Layer w0.25: B2.8 2.157,10.165 8.194,16.202 13.013,16.202 v1(14.486,17.675)
SSP1_SCK: B2.9 U1.13 | length 22.5
  Top Layer w0.25: U1.13 13.475,18.5 13.35,18.375 13.35,17.425 13.735,17.04 13.953,17.04 v1(15.02,15.973)
  Bottom Layer w0.25: B2.9 6.672,7.625 v1(15.02,15.973)
SSP1_SS/ADC1: B2.10 U1.39 | length 53.2
  Top Layer w0.25: B2.10 3.79,8.875 v1(5.3,8.875) ; v1(5.375,14.125) 5.475,14.225 5.475,33.835 v1(5.698,34.058) ; U1.39 18.625,30.6 19.035,31.01 v1(19.82,31.01)
  Signal Layer 1 w0.25: v1(5.3,8.875) 5.3,14.05 v1(5.375,14.125) ; v1(5.698,34.058) 6.384,34.744 16.087,34.744 v1(19.82,31.01)
SWDCLK_RESET-IO: JP2.4 JP4.4 U1.28 | length 43.7
  Top Layer w0.25: JP2.4 10.145,-2.255 10.397,-2.003 10.397,3.157 JP4.4@11.715,4.475 ; v1(19.135,20.901) 19.709,21.475 U1.28
  Signal Layer 1 w0.25: JP4.4@11.715,4.475 11.715,1.61 12.3,1.025 19.1,1.025 21.65,3.575 21.65,11.2 19.275,13.575 19.275,20.76 v1(19.135,20.901)
SWDIO_RESET-TGT: JP2.2 JP4.3 U1.37 | length 56.2
  Top Layer w0.25: JP2.2 8.408,-0.985 8.408,1.311 9.475,2.378 9.475,4.175 JP4.3@9.175,4.475 ; U1.37 19.625,27.098 25.383,27.098 25.434,27.149 26.882,27.149 27.458,27.725 28.795,27.725 29.185,27.335 29.185,19.56 v1(28.55,18.925)
  Bottom Layer w0.25: JP4.3@9.175,4.475 9.175,7.817 15.825,14.467 15.825,16.118 16.501,16.794 19.558,16.794 20.989,15.363 24.85,15.363 25.188,15.025 27.275,15.025 27.714,15.464 27.714,17.214 28.55,18.05 v1(28.55,18.925)
SYNC: U3.12
TX1: U1.33 U3.3 | length 28.2
  Top Layer w0.25: v1(14.451,21.151) 14.559,21.151 15.045,21.637 17.124,21.637 19.462,23.975 U1.33
  Signal Layer 1 w0.25: U3.3 6.189,30.25 7.527,28.912 7.527,20.647 v1(8.975,19.199)
  Bottom Layer w0.25: v1(8.975,19.199) 12.498,19.199 v1(14.451,21.151)
TX2: B2.21 U1.18 | length 17.4
  Top Layer w0.25: v1(16.625,17.624) U1.18
  Bottom Layer w0.25: v1(16.625,17.624) 16.874,17.375 19.55,17.375 19.725,17.2 27,17.2 27.525,17.725 27.525,19.825 28.025,20.325 B2.21
TXD0: B2.3 U1.46 | length 23
  Top Layer w0.25: B2.3 v1(2.277,25.142) ; U1.46 15.125,26.362 v1(15.553,26.133)
  Signal Layer 1 w0.25: v1(15.553,26.133) 16.899,27.479 v1(16.899,27.987)
  Bottom Layer w0.25: v1(2.277,25.142) 2.36,25.225 6.667,25.225 10.065,28.623 16.264,28.623 v1(16.899,27.987)
USB+: JP1.3 U1.20 | length 21.7
  Top Layer w0.25: v1(16.532,13.495) 18.056,15.019 18.056,16.194 17.625,16.625 U1.20
  Bottom Layer w0.25: v1(16.532,13.495) 15.807,12.77 15.807,3.75 16.807,2.75 18.75,2.75 19.158,2.342 19.158,0.608 JP1.3
USB-: JP1.2 U1.19 | length 20.7
  Top Layer w0.25: U1.19 17.125,18.225 17.167,18.225 17.167,16.21 17.525,15.852 v1(17.525,15.6)
  Bottom Layer w0.25: v1(17.525,15.6) 18.576,14.549 18.576,9.574 21.75,6.4 21.75,3.968 19.85,2.068 JP1.2
VBUS: C12.2 JP1.1 R5.1 | length 21.3
  Top Layer w0.25: R5.1 24.15,-0.775 24.15,-2.025 25.861,-3.736 C12.2 27.75,-2.986 v1(27.75,-1.75)
  Bottom Layer w0.25: JP1.1 20.65,1.3 21.725,2.375 27.725,2.375 27.725,0.6 27.15,0.025 27.15,-1.125 27.775,-1.75 v1(27.75,-1.75)
VBUS2: D6.1
WAKEUP/ADC2: B2.18 R2.1 SW3.2 U1.38 U3.15 | length 67.5
  Top Layer w0.25: SW3.2 18.35,-5.325 26.513,-5.325 v1(26.983,-4.855) ; R2.1 19.135,32.64 20.6,31.174 20.6,29.157 19.125,27.682 U1.38 19.125,26.463 19.43,26.158 21.878,26.158 22.614,25.422 25.128,25.422 U3.15 ; B2.18 28.5,10.725 28.5,9.775 29.363,8.912 v1(30.488,8.912)
  Signal Layer 1 w0.25: U3.15 27.136,24.25 28.025,23.361 28.025,23.358 28.333,23.05 28.336,23.05 29.15,22.236 29.15,18.424 28.375,17.649 28.375,14.81 B2.18
  Bottom Layer w0.25: v1(26.983,-4.855) 26.983,-3.259 28.736,-1.507 28.736,7.947 29.701,8.912 v1(30.488,8.912)
XTALIN: C7.1 U1.6 Y2.3 | length 11.6
  Top Layer w0.25: Y2.3@6.575,24.725 6.6,24.7 6.875,24.7 6.9,24.725 6.9,27 7.125,27.225 9.9,27.225 11.235,25.89 11.235,23.534 11.794,22.975 U1.6
XTALOUT: C9.1 U1.7 Y2.1 | length 6.3
  Top Layer w0.25: C9.1 8.435,21.231 8.483,21.278 Y2.1 10.473,22.315 10.633,22.475 U1.7
pads on no net: B2.0 JP1.4 JP2.6 JP2.7 JP2.8 SW1.3 SW1.4 SW2.1 SW2.3 SW2.4 SW3.3 SW3.4 U1.25 U2.4 U3.8 U3.14

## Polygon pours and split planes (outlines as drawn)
GND on GND-PLANE (split plane): 31.348,-7.223 -0.873,-7.223 -0.873,35.148 31.348,35.148

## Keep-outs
Keep-Out Layer:
  lines w0.35: -1.275,35.55 31.75,35.55 31.75,-7.615 31.74,-7.625 -1.275,-7.625 -1.275,35.565

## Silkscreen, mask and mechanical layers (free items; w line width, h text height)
Top Overlay:
  lines w0.2: 12.425,29.5 17.5,29.5 17.5,33.225 17.45,33.275 12.425,33.275 12.425,29.5
  text "20" at 23.725,33.675 h2
  text "1" at 5.65,33.625 h2
  text "11" at 23.775,15.675 h2
  text "10" at 5.6,15.625 h2
  text "CUR" at 17,6.025 h2
  text "1" at 3.8,6 h2
  text "JTAG" at 4.8,1.4 h2
  text "1" at 2.975,-1.475 h2 r90
  text "ISP" at 11.525,-6.425 h2 r90
  text "RST" at 20.275,-6.725 h2 r90
  text "WAKE" at 25.225,-6.725 h2 r90
Bottom Overlay:
  lines w0.35: 3.275,35.1 3.275,15.25 27.4,15.25 27.4,35.075 ; 17.555,6.3 17.555,7.85 20.125,7.85 20.125,6.275
  text "3.3V" at 8.25,33.625 h2
  text "DO" at 7.525,31.5 h2
  text "SCL" at 25.15,31.375 h2
  text "SCK" at 25.15,29.65 h2
  text "DI" at 6.85,29.6 h2
  text "SS" at 25.175,27.625 h2
  text "MISO" at 8.925,27.6 h2
  text "RST" at 8.25,25.75 h2
  text "PWR" at 25.225,25.6 h2
  text "SDA" at 8.375,23.825 h2
  text "WKUP" at 25.175,23.625 h2
  text "SCL" at 8.225,21.65 h2
  text "IRQ" at 25.15,19.65 h2
  text "SLP" at 8.15,17.7 h2
  text "SYNC" at 25.15,17.625 h2
  text "GND" at 8.5,15.75 h2
  text "MOSI" at 25.2,15.625 h2
  text "RESET-CPU" at 14,6.125 h2 r270
  text "J-SWDIO" at 8.825,6.1 h2 r270
  text "J-VCC" at 3.825,6.05 h2 r270
  text "J-SWCLK" at 11.5,6.05 h2 r270
  text "GND" at 6.325,6 h2 r270
Mechanical 1:
  lines w0.15: 5.1,3.4 5.1,19.375 21.1,19.375 21.1,3.4 5.1,3.4
Mechanical 2:
  lines w0.15: 201.849,96.286 201.894,96.331
Mechanical 3:
  lines w0.25: -1.275,-7.615 31.75,-7.615 31.75,35.565 -1.275,35.565 -1.275,-7.615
